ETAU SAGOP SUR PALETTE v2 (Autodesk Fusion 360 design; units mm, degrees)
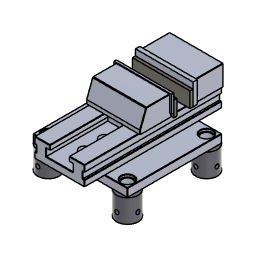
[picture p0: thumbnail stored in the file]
parameter "Ouverture" = 50
parameter "epaisseurcale" = 8
parameter "hauteurcale" = 40
base_feature "Base Feature1"
base_feature "Base Feature1"
base_feature "Base Feature1"
base_feature "Base Feature1"
as_built_joint "As-built1"
sketch "Sketch1" plane through (-65, 179, 42) normal (1, 0, 0) x axis (0, 1, 0)
  line L1 (-178, 8) -> (94, 8)
  line L2 (94, 8) -> (94, 64)
  line L3 (-6, 19) -> (-6, 64)
  line L4 (86, 48) -> (94, 48)
  line L5 (86, 8) -> (86, 48)
  line L6 (94, 8) -> (86, 8)
  line L7 (94, 48) -> (94, 8)
  line L8 (-6, 48) -> (2, 48)
  line L9 (-6, 8) -> (-6, 48)
  line L10 (2, 8) -> (-6, 8)
  line L11 (2, 48) -> (2, 8)
  point P8 (94, 48)
  point P9 (86, 48)
  point P12 (2, 48)
  point P13 (-6, 48)
  point P15 (2, 8)
  point P10 (86, 8)
  horizontal L4
  vertical L5
  horizontal L6
  vertical L7
  horizontal L8
  vertical L9
  horizontal L10
  vertical L11
  collinear L2 L7
  collinear L1 L6
  collinear L3 L9
  collinear L1 L10
  dimension "d4" distance P8 P9 = 8 (= "epaisseurcale")
  dimension "d5" distance P12 P13 = 8 (= "epaisseurcale")
  dimension "d6" distance P12 P15 = 40 (= "hauteurcale")
  dimension "d7" distance P9 P10 = 40 (= "hauteurcale")
extrude "Extrude1" new body sketch "Sketch1" profile of L4 L5 L6 L7 distance 150
extrude "Extrude1" new body sketch "Sketch1" profile of L8 L9 L10 L11 distance 150
joint "Assemble1" alignOffsetX 0 alignOffsetY 0 alignOffsetZ 50 (= "Ouverture")
base_feature "Fonction de base"
position "Position1"
rectangular_pattern "00000000-0000-0000-0000-000000000000" uSpaceDistance -206 vSpaceDistance 206
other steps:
create_component "CreateComponent1"
create_component "CreateComponent2"
create_component "CreateComponent1"
create_component "CreateComponent2"
joint_origin "JointOrigin1" OffsetX 0 OffsetY 0 OffsetZ 0
joint_origin "JointOrigin1" OffsetX 0 OffsetY 0 OffsetZ 0
create_component "CreateComponent3"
